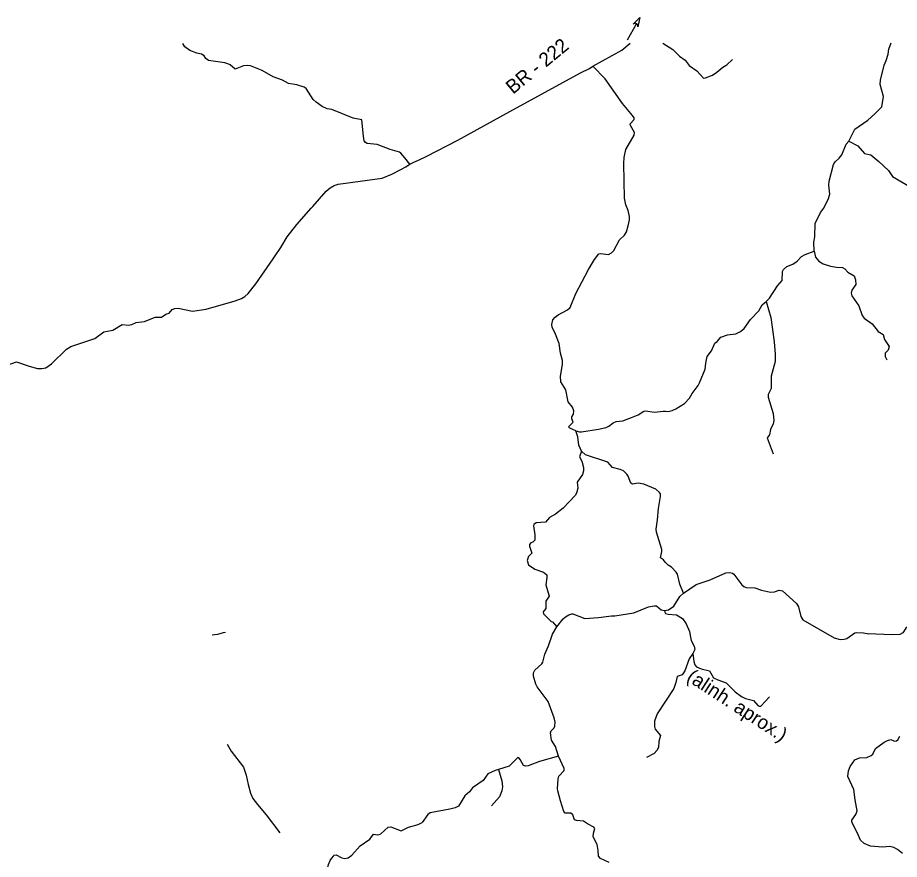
# Model space of a CAD drawing. Extents: x 332 to 501, y 9447 to 9559.
# Drawn here: x 403.82 to 427.75, y 9535.67 to 9558.53 of the extents above; entities that cross this region are included whole.
import ezdxf

# ---------------------------------------------------------------- set-up
doc = ezdxf.new("R2010")
doc.units = 0
for name, color, linetype in [('Level 12', 7, 'Continuous'), ('Level 2', 7, 'Continuous'), ('Level 31', 7, 'Continuous'), ('Level 4', 7, 'Continuous'), ('Level 5', 7, 'Continuous'), ('Level 6', 7, 'Continuous'), ('Level 7', 7, 'Continuous')]:
    doc.layers.add(name, color=color, linetype=linetype)

msp = doc.modelspace()

# ---------------------------------------------------------------- linework, layer by layer
at = {"layer": 'Level 12'}
msp.add_line((420.3653, 9557.9292), (420.6104, 9558.365), dxfattribs=at)
msp.add_lwpolyline([(420.6483, 9558.282), (420.6499, 9558.3026), (420.6473, 9558.3184), (420.6377, 9558.3396), (420.618, 9558.3607), (420.6104, 9558.365), (420.5918, 9558.3726), (420.5734, 9558.3757), (420.5549, 9558.3733), (420.5366, 9558.3663), (420.5198, 9558.3543), (420.703, 9558.5295)], close=True, dxfattribs=at)
at = {"layer": 'Level 2'}
for points in [[(419.4261, 9557.2115), (420.2112, 9557.6453), (420.4428, 9557.8379)], [(417.1785, 9555.9786), (419.092, 9557.0285), (419.3366, 9557.1496), (419.4261, 9557.2115)], [(414.9004, 9554.7598), (415.7621, 9555.2039), (417.1785, 9555.9786)], [(414.697, 9554.662), (414.9004, 9554.7598)], [(414.2183, 9554.4043), (414.3503, 9554.4806)], [(414.3503, 9554.4806), (414.3992, 9554.5095)], [(414.3992, 9554.5095), (414.3995, 9554.5097)], [(414.3995, 9554.5097), (414.4109, 9554.5165)], [(414.4109, 9554.5165), (414.4591, 9554.5459)], [(414.4591, 9554.5459), (414.5158, 9554.575)], [(414.5158, 9554.575), (414.5689, 9554.6005)], [(414.5689, 9554.6005), (414.697, 9554.662)], [(411.8257, 9553.4029), (412.1922, 9553.8139), (412.3026, 9553.9098), (412.4113, 9553.9738), (412.5121, 9554.0057), (413.7081, 9554.1656), (413.9751, 9554.276), (414.2183, 9554.4043)], [(410.9578, 9552.2871), (411.1322, 9552.5734), (411.3977, 9552.9091), (411.7868, 9553.3586)], [(411.7868, 9553.3586), (411.806, 9553.3808)], [(411.806, 9553.3808), (411.8257, 9553.4029)], [(410.7901, 9552.036), (410.9578, 9552.2871)], [(408.9336, 9550.6135), (409.722, 9550.8385), (409.8915, 9550.8992), (409.981, 9550.96), (410.0721, 9551.0335), (410.2794, 9551.2978), (410.7545, 9551.9828)], [(410.7545, 9551.9828), (410.7901, 9552.036)], [(407.2564, 9550.2739), (407.5457, 9550.3992), (407.723, 9550.3956), (407.8368, 9550.4802), (407.9256, 9550.5057), (408.0136, 9550.6006), (408.0829, 9550.6266), (408.1694, 9550.6353), (408.5579, 9550.5586), (408.9336, 9550.6135)], [(406.2532, 9550.0131), (406.3966, 9550.0432), (406.6487, 9550.194), (406.8246, 9550.1812), (406.9174, 9550.1924), (407.0293, 9550.2548), (407.2564, 9550.2739)], [(402.7875, 9548.8265), (403.7866, 9549.1802), (404.1288, 9549.0635), (404.3577, 9549.0036), (404.4742, 9548.998), (404.5829, 9549.0219), (404.7387, 9549.1247), (405.1425, 9549.524), (405.2608, 9549.5962), (405.9073, 9549.8169), (406.1595, 9549.9925), (406.2532, 9550.0131)]]:
    msp.add_lwpolyline(points, dxfattribs=at)
at = {"layer": 'Level 4'}
for points in [[(421.3257, 9557.8386), (421.5984, 9557.6669), (421.783, 9557.479), (421.9301, 9557.3751), (422.0382, 9557.2267), (422.2499, 9557.0825), (422.4322, 9556.8874), (422.4896, 9556.8921)], [(422.4896, 9556.8921), (422.6787, 9556.9694), (422.7951, 9557.0486), (422.9577, 9557.1808), (423.0692, 9557.2481), (423.2156, 9557.3965)]]:
    msp.add_lwpolyline(points, dxfattribs=at)
at = {"layer": 'Level 5'}
for points in [[(410.1361, 9557.219), (410.0511, 9557.2315), (409.9488, 9557.2171), (409.7185, 9557.1259), (409.5841, 9557.2452), (409.5201, 9557.273)], [(413.155, 9555.7581), (412.9186, 9555.7956), (412.3391, 9556.0315), (412.2152, 9556.0493), (412.0818, 9556.1189), (411.919, 9556.2325), (411.8403, 9556.3089), (411.6468, 9556.6031), (411.5893, 9556.6415), (411.3974, 9556.7086), (411.1672, 9556.7438), (411.0057, 9556.8301), (410.7498, 9556.9245), (410.4572, 9557.0956), (410.1361, 9557.219)], [(420.5454, 9555.7617), (420.5486, 9555.8049), (420.5054, 9555.8704), (420.2288, 9556.195), (419.7619, 9556.8634), (419.4261, 9557.2115)], [(414.3216, 9554.7247), (414.2191, 9554.8443), (414.1763, 9554.8737), (413.9233, 9554.9443), (413.5768, 9555.0857), (413.3003, 9555.1079), (413.2533, 9555.1379), (413.2245, 9555.1838), (413.2, 9555.3099), (413.155, 9555.7581)], [(418.4016, 9550.3992), (418.4875, 9550.4626), (418.737, 9550.5922), (418.8121, 9550.6578), (418.9704, 9551.0352), (419.3078, 9551.6875), (419.4725, 9551.9594), (419.5892, 9552.1129), (419.6324, 9552.1256), (419.8498, 9552.1001), (419.9378, 9552.1385), (420.0022, 9552.2088), (420.152, 9552.4982), (420.2895, 9552.6261), (420.3375, 9552.7141), (420.3903, 9552.8772), (420.4232, 9553.0352), (420.4257, 9553.131), (420.3855, 9553.2897), (420.3231, 9553.4432), (420.2903, 9553.6246), (420.2656, 9554.5689), (420.2816, 9554.7352), (420.3263, 9554.9526), (420.5454, 9555.3332), (420.5566, 9555.4115), (420.4487, 9555.5992), (420.4446, 9555.6466), (420.5454, 9555.7617)], [(414.4591, 9554.5459), (414.3216, 9554.7247)], [(418.3394, 9550.3194), (418.4016, 9550.3992)], [(418.3264, 9550.117), (418.3177, 9550.1985), (418.3394, 9550.3194)], [(418.9692, 9547.311), (418.7993, 9547.3777), (418.7714, 9547.4175), (418.8984, 9547.5397), (418.8553, 9547.6356), (418.8585, 9547.6868), (418.9032, 9547.762), (418.9112, 9547.8531), (418.8757, 9547.9487), (418.7609, 9548.0994), (418.6957, 9548.4184), (418.5547, 9548.643), (418.5483, 9548.7965), (418.6074, 9549.1067), (418.6026, 9549.2154), (418.5515, 9549.4201), (418.5163, 9549.6759), (418.398, 9549.9829), (418.3264, 9550.117)], [(418.9692, 9547.311), (419.064, 9547.283), (419.1207, 9547.2855), (419.5812, 9547.3494), (419.7923, 9547.4022), (419.861, 9547.431), (419.9833, 9547.5298), (420.0654, 9547.5627), (420.2387, 9547.5819), (420.4798, 9547.6692), (420.6557, 9547.746), (420.8124, 9547.8387), (420.8604, 9547.8499), (421.1002, 9547.8115), (421.3401, 9547.8435), (421.4034, 9547.8391)], [(419.1213, 9546.7591), (419.0463, 9546.9174), (419.0216, 9547.1432), (418.9692, 9547.311)], [(419.1213, 9546.7591), (419.0703, 9546.6028), (419.1303, 9546.4844), (419.1783, 9546.3165), (419.1735, 9546.2222), (419.1447, 9546.1198), (419.004, 9545.9152), (419.0176, 9545.7524), (418.988, 9545.6114), (418.9512, 9545.5554), (418.6234, 9545.2052), (418.4172, 9545.0469), (418.2541, 9544.9561), (418.1393, 9544.8313), (417.8895, 9544.8103), (417.8287, 9544.7655), (417.8143, 9544.7319), (417.8511, 9544.4825), (417.8531, 9544.341), (417.7952, 9544.2858), (417.7424, 9544.2634)], [(421.889, 9542.9029), (421.791, 9543.1457), (421.7222, 9543.4176), (421.6918, 9543.4719), (421.562, 9543.6087), (421.4732, 9543.6633), (421.3912, 9543.7406), (421.3497, 9543.8029), (421.2623, 9543.8617), (421.3026, 9544.0279), (421.2972, 9544.0874), (421.1514, 9544.5528), (421.146, 9544.6388), (421.185, 9544.8918), (421.2074, 9545.1988), (421.2669, 9545.5279), (421.2606, 9545.6012), (421.237, 9545.6366), (421.1402, 9545.7249), (420.814, 9545.8592), (420.6557, 9545.8896), (420.5022, 9545.856), (420.4574, 9545.8832), (420.3871, 9546.0751), (420.3503, 9546.1358), (420.256, 9546.2206), (420.1712, 9546.2621), (419.9602, 9546.3101), (419.8386, 9546.4604), (419.2278, 9546.6603), (419.1213, 9546.7591)], [(417.712, 9544.2218), (417.7072, 9544.1755), (417.7744, 9543.9852), (417.6736, 9543.8829), (417.6592, 9543.8429), (417.6496, 9543.7885), (417.6823, 9543.6706), (417.8576, 9543.5541), (418.0875, 9543.4726), (418.1773, 9543.4), (418.1837, 9543.3216), (418.1517, 9543.1298), (418.2429, 9542.8148), (418.1565, 9542.6788), (418.1485, 9542.4822), (418.083, 9542.3926), (418.091, 9542.3383), (418.1517, 9542.2775)], [(417.7424, 9544.2634), (417.712, 9544.2218)], [(421.889, 9542.9029), (422.2355, 9543.1329), (422.6129, 9543.2641), (423.0414, 9543.4495), (423.1501, 9543.4639), (423.2221, 9543.4463), (423.2588, 9543.4128), (423.4686, 9543.1292), (423.5291, 9543.0786), (423.5866, 9543.0562), (423.8217, 9543.0434), (424.0047, 9542.9785), (424.2517, 9542.9317), (424.362, 9542.9353), (424.4843, 9542.9781), (424.5752, 9542.9658), (424.9569, 9542.6181), (425.0086, 9542.5286)], [(421.3739, 9542.4326), (421.4777, 9542.448), (421.6247, 9542.5429), (421.791, 9542.81), (421.889, 9542.9029)], [(419.585, 9542.24), (419.9378, 9542.2855), (420.0258, 9542.2801), (420.5438, 9542.3654), (420.9371, 9542.5285), (421.0906, 9542.5557), (421.1594, 9542.5525), (421.2841, 9542.4518), (421.3739, 9542.4326)], [(425.0086, 9542.5286), (425.0753, 9542.2695), (425.1312, 9542.18), (425.9771, 9541.6859), (426.1402, 9541.6459), (426.2489, 9541.6491), (426.3241, 9541.6731), (426.5351, 9541.8186), (426.5975, 9541.8314), (426.7702, 9541.825), (426.9221, 9541.7915)], [(418.1517, 9542.2775), (418.2956, 9542.1352), (418.3308, 9542.1208), (418.4475, 9541.9832)], [(418.4475, 9541.9832), (418.6202, 9542.204), (418.6826, 9542.2599), (418.7721, 9542.3159), (418.8553, 9542.3351), (418.8889, 9542.3367), (419.2134, 9542.2119), (419.585, 9542.24)], [(421.3739, 9542.4326), (421.3798, 9542.3815), (421.4014, 9542.352), (421.4756, 9542.3299), (421.695, 9542.3079), (421.8629, 9542.2167), (421.9573, 9542.068), (422.0516, 9541.8634), (422.0808, 9541.7009)], [(418.2962, 9539.1605), (418.3804, 9539.2395), (418.3996, 9539.2858), (418.4044, 9539.401), (418.3788, 9539.5161), (418.2109, 9539.9558), (417.9199, 9540.3587), (417.8831, 9540.4307), (417.8207, 9540.6482), (417.8159, 9540.7361), (417.8495, 9540.808), (418.0462, 9540.9823), (418.075, 9541.0255), (418.1293, 9541.2462), (418.2237, 9541.4668), (418.33, 9541.7851), (418.4475, 9541.9832)], [(422.0808, 9541.7009), (422.0968, 9541.6107), (422.1811, 9541.4652), (422.1955, 9541.3661), (422.1457, 9541.2581)], [(422.1457, 9541.2581), (422.0415, 9541.1184), (421.9205, 9540.7889), (421.8501, 9540.6833), (421.7206, 9540.6402), (421.6822, 9540.4755), (421.6231, 9540.3124), (421.1722, 9539.6216), (421.1004, 9539.421), (421.1002, 9539.2826), (421.1216, 9539.2078)], [(422.1457, 9541.2581), (422.1662, 9541.0408), (422.1992, 9540.9538), (422.2444, 9540.9015), (422.3666, 9540.8464), (422.5969, 9540.7904), (422.7072, 9540.605), (422.8207, 9540.5426), (423.051, 9540.4611), (423.2892, 9540.2228), (423.4635, 9540.0981), (423.5722, 9540.0421), (423.7881, 9539.983), (423.9073, 9539.8503), (423.946, 9539.8272), (423.9853, 9539.8272), (424.2221, 9540.0877)], [(418.4999, 9538.4696), (418.4124, 9538.7366), (418.3068, 9538.9053), (418.278, 9539.1099), (418.2962, 9539.1605)], [(421.1216, 9539.2078), (421.2601, 9539.038), (421.2201, 9538.8733), (421.2058, 9538.707), (421.1674, 9538.6286), (421.0906, 9538.5439), (420.8885, 9538.4348)], [(418.4999, 9538.4696), (417.9822, 9538.3312), (417.6752, 9538.2113), (417.5985, 9538.2017), (417.5473, 9538.2241), (417.4578, 9538.3872), (417.4226, 9538.4272), (417.389, 9538.4352), (417.154, 9538.2065), (416.866, 9538.1143)], [(419.8754, 9535.5842), (419.6324, 9535.6961), (419.5812, 9535.7569), (419.5732, 9535.912), (419.5409, 9536.0715), (419.4373, 9536.283), (419.4469, 9536.3853), (419.4837, 9536.5052), (419.4533, 9536.55), (419.287, 9536.6331), (419.1735, 9536.7099), (418.98, 9536.7227), (418.9288, 9536.7419), (418.8841, 9536.8826), (418.8265, 9536.9226), (418.6794, 9536.9273), (418.6426, 9536.9673), (418.5483, 9537.2583), (418.4747, 9537.5302), (418.4731, 9537.5845), (418.4875, 9537.8564), (418.5067, 9537.9299), (418.6474, 9538.0834), (418.6538, 9538.1378), (418.4999, 9538.4696)], [(416.7804, 9538.0869), (416.5815, 9537.9923), (416.4503, 9537.8154), (416.1594, 9537.6117), (416.0827, 9537.5094), (415.9563, 9537.3959), (415.7805, 9537.116), (415.6925, 9537.0681), (415.5486, 9537.0313), (415.0146, 9536.9337), (414.9506, 9536.889), (414.7936, 9536.6754)], [(416.866, 9538.1143), (416.9602, 9537.8072), (416.9746, 9537.6441), (416.9618, 9537.5354), (416.8915, 9537.3723), (416.6751, 9537.1215)], [(416.866, 9538.1143), (416.7804, 9538.0869)], [(411.9269, 9534.7388), (411.9349, 9534.7815), (411.9854, 9534.84), (412.1956, 9535.298), (412.2499, 9535.5283), (412.2963, 9535.6434), (412.3432, 9535.7039)], [(412.3432, 9535.7039), (412.3851, 9535.7579)]]:
    msp.add_lwpolyline(points, dxfattribs=at)
at = {"layer": 'Level 6'}
for points in [[(426.3747, 9555.176), (426.5397, 9555.4966), (426.8882, 9555.7492), (427.0849, 9555.9155), (427.2675, 9556.1112), (427.3135, 9556.3888), (427.224, 9556.7102), (427.2336, 9556.8302), (427.3383, 9557.2388), (427.3935, 9557.361), (427.4431, 9557.5353), (427.4607, 9557.6744), (427.5223, 9557.8437)], [(425.6078, 9553.2386), (425.697, 9553.3556), (425.8265, 9553.6194), (425.8585, 9553.7361), (425.8361, 9553.9792), (425.8457, 9554.0911), (425.9608, 9554.5388), (426.0008, 9554.6124), (426.1159, 9554.7099), (426.1863, 9554.8075), (426.303, 9555.0921), (426.3747, 9555.176)], [(426.3747, 9555.176), (426.6164, 9555.0457), (426.8051, 9554.8442), (426.9746, 9554.8058), (427.1888, 9554.6268), (427.4511, 9554.3773), (427.522, 9554.2707)], [(425.4361, 9552.183), (425.4286, 9552.4327), (425.4494, 9552.5766), (425.4638, 9552.9379), (425.6078, 9553.2386)], [(424.1288, 9550.8243), (424.2218, 9550.9137), (424.4437, 9551.243), (424.57, 9551.3917), (424.5796, 9551.6396), (424.5988, 9551.6907), (424.6963, 9551.7691), (424.8578, 9551.8314), (424.9761, 9551.9194), (425.0935, 9552.0397), (425.1938, 9552.1006), (425.4361, 9552.183)], [(425.4361, 9552.183), (425.467, 9552.0201), (425.5578, 9551.9151), (425.6829, 9551.8458), (425.8748, 9551.7787), (426.0378, 9551.7515), (426.2057, 9551.7467), (426.2665, 9551.7067), (426.3464, 9551.6156), (426.5223, 9551.5196), (426.5543, 9551.4125), (426.5655, 9551.2846), (426.4568, 9551.1311), (426.4392, 9551.0512), (426.4536, 9550.9776), (426.6471, 9550.7042), (426.742, 9550.4424), (426.7934, 9550.3654), (427.0052, 9550.2164), (427.1731, 9550.0069), (427.3106, 9549.927), (427.3426, 9549.7927), (427.4673, 9549.6008), (427.4417, 9549.4953), (427.3618, 9549.4185), (427.3634, 9549.3274), (427.4051, 9549.2353)], [(422.8979, 9549.8543), (423.0827, 9549.916), (423.306, 9549.9468), (423.4318, 9550.0033), (423.5319, 9550.0881), (423.7081, 9550.3297), (423.9358, 9550.5632), (424.0201, 9550.7299), (424.0854, 9550.7825)], [(424.0854, 9550.7825), (424.1288, 9550.8243)], [(424.1288, 9550.8243), (424.2617, 9550.3823), (424.3514, 9549.7275), (424.3737, 9549.3949), (424.3738, 9549.1887), (424.2682, 9548.7937), (424.2714, 9548.458), (424.1899, 9548.2981), (424.1883, 9548.2245), (424.3258, 9547.7768), (424.3386, 9547.5881), (424.3202, 9547.4954), (424.2458, 9547.3483), (424.2256, 9547.1991), (424.1563, 9547.1212), (424.321, 9546.6815)], [(421.4034, 9547.8391), (421.4767, 9547.8324), (421.5834, 9547.8569), (421.6839, 9547.9059), (421.9141, 9548.0466), (422.05, 9548.1921), (422.122, 9548.3216), (422.2867, 9548.5391), (422.3266, 9548.6142), (422.4781, 9548.9865), (422.4909, 9549.1483), (422.5268, 9549.323), (422.6496, 9549.4793), (422.7408, 9549.6935), (422.7999, 9549.7303), (422.8979, 9549.8543)]]:
    msp.add_lwpolyline(points, dxfattribs=at)
at = {"layer": 'Level 7'}
for points in [[(409.5201, 9557.273), (409.4355, 9557.3018), (408.9958, 9557.361), (408.927, 9557.4186), (408.8742, 9557.4889), (408.8055, 9557.5385), (408.676, 9557.5657), (408.4889, 9557.6328), (408.3514, 9557.7336), (408.3037, 9557.8265)], [(427.522, 9554.2707), (427.5616, 9554.2177), (428.0871, 9553.9095)], [(429.662, 9542.2974), (429.6852, 9542.2279), (429.5717, 9542.132), (429.3814, 9542.18), (429.2455, 9542.2471), (429.1064, 9542.2679), (428.9494, 9542.2612), (428.7158, 9542.2792), (428.5161, 9542.253), (428.3068, 9542.1416), (428.2252, 9542.0808), (427.971, 9541.9833), (427.9262, 9541.9488), (427.8397, 9541.826), (427.7647, 9541.7786), (427.545, 9541.7671), (427.1058, 9541.7855)], [(409.4537, 9541.83), (409.3944, 9541.8266), (409.2409, 9541.777), (409.0938, 9541.7611)], [(427.1058, 9541.7855), (426.9221, 9541.7915)], [(427.8367, 9535.8273), (427.6992, 9535.9424), (427.601, 9535.9933), (427.4889, 9536.0233), (427.2914, 9536.0063), (426.9684, 9536.0319), (426.791, 9536.1039), (426.6966, 9536.1886), (426.6158, 9536.3818), (426.4584, 9536.6843), (426.4568, 9536.7323), (426.5671, 9536.8858), (426.6028, 9536.9894), (426.5447, 9537.2871), (426.5143, 9537.5717), (426.3528, 9537.9251), (426.3656, 9538.0738), (426.4104, 9538.1921), (426.5413, 9538.3742), (426.6662, 9538.4309), (426.8679, 9538.4364), (426.9812, 9538.4895), (427.0308, 9538.5295), (427.1012, 9538.683), (427.3362, 9538.8525), (427.4226, 9538.9005), (427.5169, 9538.9229), (427.6144, 9538.8829), (427.6672, 9538.8893), (427.7072, 9538.9213), (427.7615, 9539.0188)], [(409.4997, 9538.7952), (409.6112, 9538.6116), (409.9453, 9538.1719), (410.0189, 9537.9576), (410.0701, 9537.7034), (410.1404, 9537.4651), (410.2028, 9537.3244), (410.3227, 9537.1581), (410.5657, 9536.8831), (410.933, 9536.3884)], [(412.3851, 9535.7579), (412.4005, 9535.7838), (412.4642, 9535.7905), (412.6145, 9535.7089), (412.6944, 9535.6961), (412.7872, 9535.7105), (412.8863, 9535.7841), (413.1134, 9536.0399), (413.3772, 9536.219), (413.4711, 9536.3583), (413.5811, 9536.337), (413.6313, 9536.3456), (413.673, 9536.3629), (413.8729, 9536.5436), (413.9423, 9536.5514)], [(413.9423, 9536.5514), (414.2247, 9536.4477), (414.4213, 9536.5452), (414.69, 9536.614), (414.7936, 9536.6754)]]:
    msp.add_lwpolyline(points, dxfattribs=at)

# ---------------------------------------------------------------- texts
at = {"layer": 'Level 31'}
for s, rotation, p in [('BR - 222', 39.38902, (417.26, 9556.4343)), ('(alinh. aprox.)', 326.92236, (421.9452, 9540.5454))]:
    msp.add_text(s, height=0.38, rotation=rotation, dxfattribs=at).set_placement(p)

doc.saveas('drawing.dxf')
